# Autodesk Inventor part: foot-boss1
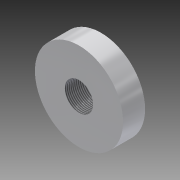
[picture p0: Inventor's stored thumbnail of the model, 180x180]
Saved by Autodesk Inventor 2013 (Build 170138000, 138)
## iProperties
Created: 2012-11
Part Number: foot-boss1
Material: Stainless Steel, 316
Description: FOOT BOSS
Document SubType Name: Modeling
Designer: Henneborn
Manufacturer: Standard
Standards Organization: Custom
Mass: 1626.81 g
Surface Area: 243.22 cm^2
Volume: 205.926 cm^3
Density: 7.9 g/cm^3
Rohmasse: 4" O.D. x 1"  THK. PLATE
Author: vm
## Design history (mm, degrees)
sketch "Sketch1"
  geometry: C1 r 50.8 at (0, 0); 1 further point
  constraints: 1 centre point, 1 coincident
  dimensions: "d0" = 101.6 diameter of C1
extrude "Extrusion1" new body sketch "Sketch1" stored distance "d1" = 25.4; taper "d2" = 0 deg
hole "Hole1" diameter "d5" = 32.639; stored, may be unused: countersink angle "d9" = 82 deg, drill point angle "d11" = 118 deg; dims "d6" = 19.05, "d7" = 9.525, "d8" = 6.35, "d10" = 25.4, "d12" = 25.4, "d13" = 25.4
body "Solid1"
